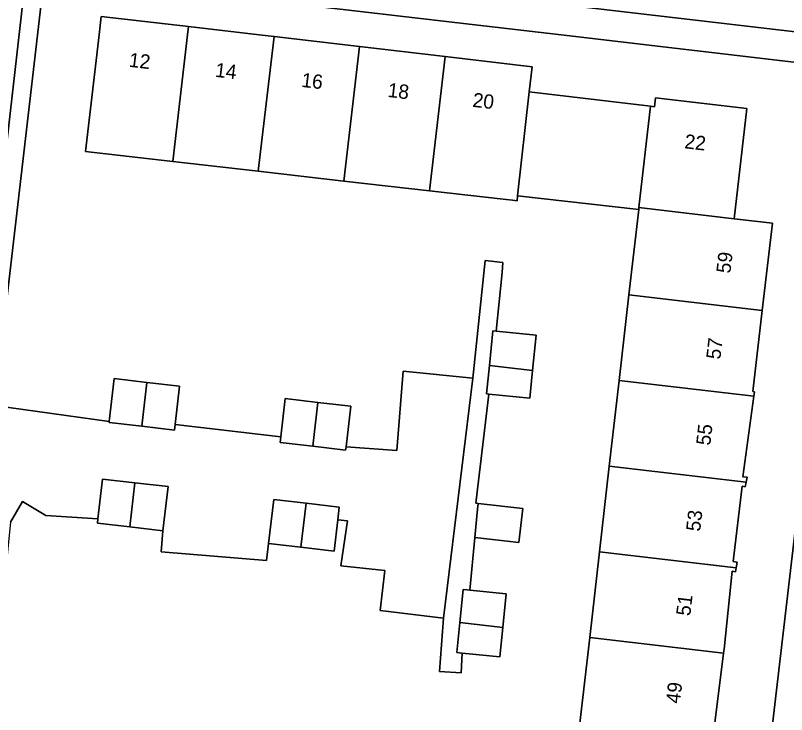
# Model space of a CAD drawing. Extents: x 161241 to 161758, y 384138 to 384885.
# Drawn here: x 161339.7 to 161393.7, y 384452.3 to 384501.4 of the extents above; entities that cross this region are included whole.
import ezdxf

# ---------------------------------------------------------------- set-up
doc = ezdxf.new("R2010")
doc.units = 0
for name, color, linetype in [('IMGEO_Erf', 7, 'Continuous'), ('IMGEO_Pand', 7, 'Continuous'), ('IMGEO_Pand_nummerreeks', 7, 'Continuous'), ('IMGEO_Rijbaan_lokaal_open', 7, 'Continuous'), ('IMGEO_Voetpad_open', 7, 'Continuous')]:
    doc.layers.add(name, color=color, linetype=linetype)

msp = doc.modelspace()

# ---------------------------------------------------------------- linework, layer by layer
at = {"layer": 'IMGEO_Erf'}
for points in [[(161332.131, 384432.245), (161332.897, 384438.907), (161336.632, 384471.394), (161336.946, 384474.139), (161340.403, 384504.377), (161340.647, 384506.515), (161340.82, 384506.489), (161349.943, 384584.816), (161350.191, 384586.943), (161382.92, 384583.217)], [(161395.453, 384497.957), (161377.935, 384500), (161341.704, 384504.225), (161338.179, 384473.999), (161346.237, 384472.872), (161346.586, 384475.89), (161348.88, 384475.625), (161351.176, 384475.359), (161350.864, 384472.665), (161358.276, 384471.808), (161358.586, 384474.488), (161360.88, 384474.222), (161363.176, 384473.957), (161362.847, 384471.116), (161366.412, 384470.853), (161366.853, 384476.421), (161371.732, 384475.931), (161372.614, 384484.169), (161373.84, 384484.035), (161373.791, 384483.323), (161373.38, 384479.219), (161376.18, 384478.939), (161375.932, 384476.461), (161375.737, 384474.51), (161372.872, 384474.797), (161371.946, 384467.158), (161372.118, 384467.138), (161375.247, 384466.773), (161374.97, 384464.395), (161374.149, 384464.491), (161371.88, 384464.756), (161371.54, 384461.05), (161374.086, 384460.796), (161373.851, 384458.437), (161373.644, 384456.367), (161370.993, 384456.632), (161370.917, 384455.254), (161369.398, 384455.338), (161369.687, 384459.099), (161365.23, 384459.635), (161365.566, 384462.431), (161362.481, 384462.751), (161362.947, 384465.913), (161362.262, 384465.992), (161362.007, 384463.791), (161359.683, 384464.059), (161357.417, 384464.321), (161357.28, 384463.143), (161349.875, 384463.751), (161350.003, 384465.226)], [(161379.251, 384451.718), (161379.938, 384457.726), (161380.625, 384463.735), (161381.312, 384469.744), (161381.999, 384475.753), (161382.686, 384481.762), (161383.37, 384487.744), (161374.878, 384488.715), (161374.838, 384488.36), (161374.517, 384488.396), (161374.066, 384488.448), (161368.697, 384489.062), (161362.696, 384489.749), (161356.694, 384490.435), (161350.692, 384491.122), (161344.577, 384491.822), (161345.523, 384500), (161345.673, 384501.293), (161351.799, 384500.579), (161356.763, 384500), (161357.799, 384499.879), (161363.8, 384499.18), (161369.8, 384498.48), (161375.908, 384497.768), (161375.697, 384496.013), (161384.199, 384494.997), (161384.49, 384494.962), (161384.54, 384495.588), (161390.958, 384494.84), (161390.059, 384487.105), (161392.751, 384486.785), (161392.036, 384480.67), (161391.371, 384474.976), (161391.486, 384474.955), (161391.445, 384474.65), (161390.678, 384469.01), (161390.98, 384468.975), (161390.911, 384468.623), (161390.849, 384468.311), (161390.638, 384468.352), (161389.986, 384463.054), (161390.269, 384463.022), (161390.201, 384462.616), (161390.155, 384462.338), (161389.918, 384462.39), (161389.363, 384456.913), (161389.327, 384456.63), (161388.569, 384450.629)], [(161390.869, 384435.421), (161397.785, 384494.638)], [(161350.003, 384465.226), (161347.677, 384465.495), (161345.413, 384465.757), (161345.447, 384466.051), (161341.804, 384466.297), (161340.159, 384467.275), (161339.305, 384465.833), (161336.535, 384438.485), (161387.488, 384432.576)]]:
    msp.add_lwpolyline(points, dxfattribs=at)
at = {"layer": 'IMGEO_Pand'}
for points in [[(161351.731, 384500), (161351.799, 384500.579), (161345.673, 384501.293), (161345.523, 384500), (161344.577, 384491.822), (161350.692, 384491.122)], [(161357.799, 384499.879), (161356.763, 384500), (161351.799, 384500.579), (161351.731, 384500), (161350.692, 384491.122), (161356.694, 384490.435)], [(161363.8, 384499.18), (161357.799, 384499.879), (161356.694, 384490.435), (161362.696, 384489.749)], [(161369.8, 384498.48), (161363.8, 384499.18), (161362.696, 384489.749), (161368.697, 384489.062)], [(161375.697, 384496.013), (161375.908, 384497.768), (161369.8, 384498.48), (161368.697, 384489.062), (161374.066, 384488.448), (161374.517, 384488.396), (161374.838, 384488.36), (161374.878, 384488.715)], [(161384.199, 384494.997), (161375.697, 384496.013), (161374.878, 384488.715), (161383.37, 384487.744), (161383.388, 384487.899)], [(161383.388, 384487.899), (161390.059, 384487.105), (161390.958, 384494.84), (161384.54, 384495.588), (161384.49, 384494.962), (161384.199, 384494.997)], [(161383.37, 384487.744), (161382.686, 384481.762), (161392.036, 384480.67), (161392.751, 384486.785), (161390.059, 384487.105), (161383.388, 384487.899)], [(161391.445, 384474.65), (161391.486, 384474.955), (161391.371, 384474.976), (161392.036, 384480.67), (161382.686, 384481.762), (161381.999, 384475.753)], [(161376.18, 384478.939), (161373.38, 384479.219), (161373.151, 384479.242), (161372.908, 384476.815), (161375.932, 384476.461)], [(161375.932, 384476.461), (161372.908, 384476.815), (161372.708, 384474.813), (161372.872, 384474.797), (161375.737, 384474.51)], [(161348.88, 384475.625), (161346.586, 384475.89), (161346.237, 384472.872), (161346.23, 384472.815), (161348.52, 384472.55)], [(161348.88, 384475.625), (161348.52, 384472.55), (161350.82, 384472.284), (161350.864, 384472.665), (161351.176, 384475.359)], [(161390.911, 384468.623), (161390.98, 384468.975), (161390.678, 384469.01), (161391.445, 384474.65), (161381.999, 384475.753), (161381.312, 384469.744)], [(161360.88, 384474.222), (161358.586, 384474.488), (161358.276, 384471.808), (161358.23, 384471.41), (161360.52, 384471.145)], [(161360.88, 384474.222), (161360.52, 384471.145), (161362.82, 384470.879), (161362.847, 384471.116), (161363.176, 384473.957)], [(161381.312, 384469.744), (161380.625, 384463.735), (161390.201, 384462.616), (161390.269, 384463.022), (161389.986, 384463.054), (161390.638, 384468.352), (161390.849, 384468.311), (161390.911, 384468.623)], [(161348.036, 384468.585), (161345.771, 384468.848), (161345.447, 384466.051), (161345.413, 384465.757), (161347.677, 384465.495)], [(161348.036, 384468.585), (161347.677, 384465.495), (161350.003, 384465.226), (161350.361, 384468.316)], [(161360.042, 384467.15), (161357.775, 384467.413), (161357.417, 384464.321), (161359.683, 384464.059)], [(161362.262, 384465.992), (161362.365, 384466.881), (161360.042, 384467.15), (161359.683, 384464.059), (161362.007, 384463.791)], [(161372.118, 384467.138), (161372.078, 384466.736), (161371.88, 384464.756), (161374.149, 384464.491), (161374.97, 384464.395), (161375.247, 384466.773)], [(161389.327, 384456.63), (161389.363, 384456.913), (161389.918, 384462.39), (161390.155, 384462.338), (161390.201, 384462.616), (161380.625, 384463.735), (161379.938, 384457.726)], [(161374.086, 384460.796), (161371.54, 384461.05), (161371.333, 384461.071), (161371.057, 384461.099), (161370.826, 384458.79), (161373.851, 384458.437)], [(161373.851, 384458.437), (161370.826, 384458.79), (161370.614, 384456.67), (161370.993, 384456.632), (161373.644, 384456.367)], [(161379.938, 384457.726), (161379.251, 384451.718), (161388.569, 384450.629), (161389.327, 384456.63)]]:
    msp.add_lwpolyline(points, close=True, dxfattribs=at)
at = {"layer": 'IMGEO_Rijbaan_lokaal_open'}
msp.add_lwpolyline([(161357.65, 384509.288), (161357.097, 384504.581), (161396.178, 384500), (161427.321, 384496.383), (161427.741, 384500), (161427.862, 384501.04), (161424.463, 384501.437), (161370.122, 384507.816)], close=True, dxfattribs=at)
msp.add_lwpolyline([(161339.305, 384465.833), (161340.159, 384467.275), (161341.804, 384466.297), (161345.447, 384466.051), (161345.771, 384468.848), (161348.036, 384468.585), (161350.361, 384468.316), (161350.003, 384465.226), (161349.875, 384463.751), (161357.28, 384463.143), (161357.417, 384464.321), (161357.775, 384467.413), (161360.042, 384467.15), (161362.365, 384466.881), (161362.262, 384465.992), (161362.947, 384465.913), (161362.481, 384462.751), (161365.566, 384462.431), (161365.23, 384459.635), (161369.687, 384459.099), (161371.732, 384475.931), (161366.853, 384476.421), (161366.412, 384470.853), (161362.847, 384471.116), (161362.82, 384470.879), (161360.52, 384471.145), (161358.23, 384471.41), (161358.276, 384471.808), (161350.864, 384472.665), (161350.82, 384472.284), (161348.52, 384472.55), (161346.23, 384472.815), (161346.237, 384472.872), (161338.179, 384473.999)], dxfattribs=at)
at = {"layer": 'IMGEO_Voetpad_open'}
for points in [[(161430.062, 384496.065), (161427.321, 384496.383), (161396.178, 384500), (161357.097, 384504.581), (161354.376, 384504.9), (161340.82, 384506.489), (161340.647, 384506.515), (161340.403, 384504.377), (161341.704, 384504.225), (161377.935, 384500), (161395.453, 384497.957), (161401.111, 384497.3), (161421.466, 384494.929), (161433, 384493.585), (161437.975, 384493.006), (161442.515, 384492.47), (161448.511, 384491.779), (161454.323, 384491.094), (161500, 384485.79), (161510.344, 384484.589), (161510.654, 384486.641), (161500, 384487.889), (161448.776, 384493.891)], [(161341.704, 384504.225), (161340.403, 384504.377), (161336.946, 384474.139), (161338.179, 384473.999)], [(161372.872, 384474.797), (161372.708, 384474.813), (161372.908, 384476.815), (161373.151, 384479.242), (161373.38, 384479.219), (161373.791, 384483.323), (161373.84, 384484.035), (161372.614, 384484.169), (161371.732, 384475.931), (161369.687, 384459.099), (161369.398, 384455.338), (161370.917, 384455.254), (161370.993, 384456.632), (161370.614, 384456.67), (161370.826, 384458.79), (161371.057, 384461.099), (161371.333, 384461.071), (161371.54, 384461.05), (161371.88, 384464.756), (161372.078, 384466.736), (161372.118, 384467.138), (161371.946, 384467.158)]]:
    msp.add_lwpolyline(points, close=True, dxfattribs=at)
msp.add_lwpolyline([(161397.785, 384494.638), (161390.869, 384435.421)], dxfattribs=at)

# ---------------------------------------------------------------- texts
at = {"layer": 'IMGEO_Pand_nummerreeks'}
for s, rotation, p in [('12', 353.348, (161347.584, 384497.768)), ('14', 353.348, (161353.634, 384497.063)), ('16', 353.348, (161359.681, 384496.358)), ('18', 353.348, (161365.73, 384495.652)), ('20', 353.348, (161371.687, 384494.958)), ('22', 353.3523, (161386.545, 384492.051)), ('59', 83.3157, (161389.799, 384483.24)), ('57', 83.3157, (161389.092, 384477.205)), ('55', 83.3157, (161388.384, 384471.17)), ('53', 83.3157, (161387.677, 384465.135)), ('51', 83.3157, (161386.983, 384459.211)), ('49', 83.3157, (161386.263, 384453.064))]:
    msp.add_text(s, height=1, rotation=rotation, dxfattribs=at).set_placement(p)

doc.saveas('drawing.dxf')
